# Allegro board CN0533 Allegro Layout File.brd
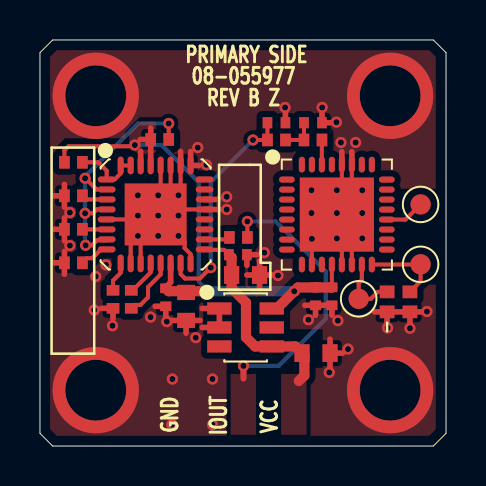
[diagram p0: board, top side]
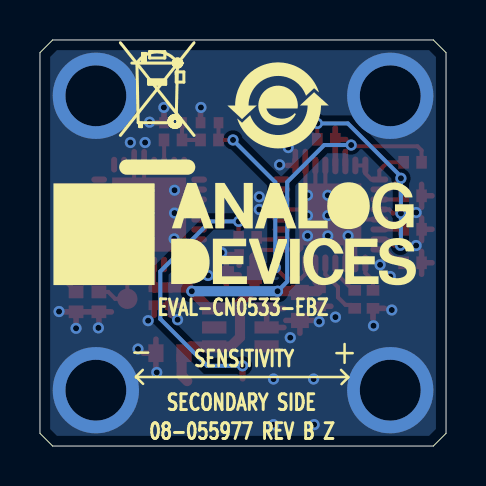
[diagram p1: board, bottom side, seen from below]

Outline 20.32 x 20.32 mm; copper layers: TOP, BOTTOM. Coordinates in mm from the lower left corner of the outline.
Outline path: 0,19.68 0.63,20.32 19.69,20.32 20.32,19.68 20.32,0.64 19.69,0 0.63,0 0,0.64 0,19.68

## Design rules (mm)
constraint set DEFAULT: min track width 0.203

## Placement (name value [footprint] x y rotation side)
C1  4700PF  [C0402]  13.66 16.18 180 top
C2  4700PF  [C0402]  11.83 16.18 180 top
C3  0.1uF  [C0402]  14.61 7.49 90 top
C4  1uF  [C0402]  13.79 7.49 90 top
C5  1uF  [C0603]  13.82 4.65 180 top
C6  0.1UF  [C0402]  9.9 9.58 180 top
C7  10UF  [C0603]  10.29 8.56 180 top
C8  0.1UF  [C0402]  6.3 7.44 90 top
C9  10uF  [C0603]  7.31 6.98 90 top
NOREF  -  []  19.69 0 90 top
NOREF#2  -  []  2.79 2.79 0 top
NOREF#3  -  []  -330.41 -227.36 0 top
NOREF#4  -  []  -233.94 -118.87 0 top
NOREF#5  -  []  11.61 28.17 0 top
NOREF#6  -  []  -206.25 31.75 0 top
NOREF#7  -  []  0.63 0 0 top
NOREF#8  -  []  0 0.64 0 top
NOREF#9  -  []  0 19.68 0 top
NOREF#10  -  []  61.64 260.07 0 top
NOREF#11  -  []  -330.41 -227.36 0 top
NOREF#12  -  []  -202.72 -33.5 0 top
NOREF#13  -  []  20.32 20.32 180 top
NOREF#14  -  []  -199.01 -56.36 0 top
NOREF#15  -  []  0 19.68 0 top
NOREF#16  -  []  2.79 2.79 0 top
NOREF#17  -  []  0 0 0 top
NOREF#18  -  []  20.32 0 90 top
NOREF#19  -  []  20.32 0.64 0 top
NOREF#20  -  []  0.63 20.32 0 top
NOREF#21  -  []  -46.48 223.98 0 top
NOREF#22  -  []  0 20.32 270 top
NOREF#23  -  []  19.69 0 0 top
NOREF#24  -  []  -198.96 -79.22 0 top
NOREF#25  -  []  10.08 9.32 180 bottom
NOREF#26  -  []  8.4 17.04 180 bottom
NOREF#27  -  []  14.65 13.64 180 bottom
R1  680  [R0402]  13.66 15.32 180 top
R2  1.3K  [R0402]  11.83 15.32 180 top
R3  15K  [R0402]  4.57 7.34 90 top
R4  0  [R0402]  3.66 7.34 270 top
R5  0  [R0402]  1.67 9.17 0 top
R6  0  [R0402]  1.67 10.85 0 top
R7  0  [R0402]  1.67 12.52 0 top
R8  100K  [R0402]  1.67 14.2 0 top
R9  0  [R0402]  9.93 10.44 0 top
R10  0  [R0402]  5.99 15.34 0 top
R11  470K  [R0402]  17.37 7.21 90 top
R12  470K  [R0402]  18.51 7.21 90 top
TP1  TESTPAD  [TPSMC40]  19.05 12.09 270 top
TP2  TESTPAD  [TPSMC40]  19.05 9.09 270 top
TP3  TESTPAD  [TPSMC40]  15.95 7.37 270 top
U1  ADXL1002BCPZ  [QFN32_5X5_PAD3_7X3_7]  14.86 11.58 270 top
U2  LT6654AMPS6-5#TRMPBF  [TSOT23_6]  10.29 5.93 270 top
U3  AD5749ACPZ  [QFN32_5X5_PAD3_1X3_1]  5.79 11.59 270 top

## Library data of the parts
C1 C2 = CAP: User Part Number: UPN; Tolerance: 10; alternate symbols: C0402L; part number: CAP_SM-4700PF,50V,10,E028612,C0402; tolerance: 10
C3 = CAP: User Part Number: UPN; Tolerance: 10; alternate symbols: C0402L; part number: CAP_SM-0.1UF,10V,10,E016510,C0402; tolerance: 10
C4 = CAP: User Part Number: UPN; Tolerance: 10; alternate symbols: C0402L; part number: CAP_SM-1UF,6.3V,10,E011561,C0402; tolerance: 10
C5 = CAP: User Part Number: UPN; Tolerance: 10; alternate symbols: C0603L; part number: CAP_SM-1UF,50V,10,E023087,C0603; tolerance: 10
C6 = CAP: User Part Number: UPN; Tolerance: 10; alternate symbols: C0402L; part number: CAP_SM-0.1UF,50V,10,E034665,C0402; tolerance: 10
C7 = CAP: User Part Number: UPN; Tolerance: 20; alternate symbols: C0603L; part number: CAP_SM-10UF,35V,20,E026762,C0603; tolerance: 20
C8 = CAP: User Part Number: UPN; Tolerance: 10; alternate symbols: C0402L; part number: CAP_SM-0.1UF,25V,10,E026964,C0402; tolerance: 10
C9 = CAP: User Part Number: UPN; Tolerance: 20; alternate symbols: C0603L; part number: CAP_SM-10UF,25V,20,E023693,C0603; tolerance: 20
R1 = RES: User Part Number: UPN; Tolerance: 1; alternate symbols: R0402L; part number: RES_SM-680,E015602,1/10W,1,R0402; tolerance: 1
R2 = RES: User Part Number: UPN; Tolerance: 1; alternate symbols: R0402L; part number: RES_SM-1.3K,E015613,1/10W,1,R0402; tolerance: 1
R3 = RES: User Part Number: UPN; Tolerance: 1; alternate symbols: R0402L; part number: RES_SM-15K,E007441,1/16W,1,R0402; tolerance: 1
R4-R7 R9 R10 = RES: User Part Number: UPN; Tolerance: 5; alternate symbols: R0402L; part number: RES_SM-0,E003438,N/A,5,R0402; tolerance: 5
R8 = RES: User Part Number: UPN; Tolerance: 5; alternate symbols: R0402L; part number: RES_SM-100K,E003464,1/10W,5,R0402; tolerance: 5
R11 R12 = RES: User Part Number: UPN; Tolerance: 5; alternate symbols: R0402L; part number: RES_SM-470K,E027137,1/10W,5,R0402; tolerance: 5
TP1-TP3 = NCTESTPAD: Tolerance: N/A; User Part Number: UPN; alternate symbols: (); part number: NCTESTPAD_SM-TESTPAD,E019801,TPSMC40; tolerance: N/A
U1 = ADXL100X: User Part Number: UPN; Tolerance: N/A; alternate symbols: (); part number: ADXL100X_SM-ADXL1002BCPZ,E026572,QFN32_5X5_PAD3_7X3_7; tolerance: N/A
U2 = LINLT6654: User Part Number: UPN; Tolerance: N/A; alternate symbols: (); part number: LINLT6654_SM-LT6654AMPS6-5#TRMPBF,E030329,TSOT23_6; tolerance: N/A
U3 = AD5749: User Part Number: UPN; Tolerance: N/A; alternate symbols: (); part number: AD5749_SM-AD5749ACPZ,E034718,QFN32_5X5_PAD3_1X3_1; tolerance: N/A

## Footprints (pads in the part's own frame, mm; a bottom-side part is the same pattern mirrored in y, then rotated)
C0402
  rect 0.483x0.559 smd: 1(-0.45,0) 2(0.45,0)
C0603
  rect 0.762x0.889 smd: 1(-0.7,0) 2(0.7,0)
QFN32_5X5_PAD3_1X3_1
  oval 0.305x0.889 smd: 1(-1.75,-2.45) 2(-1.25,-2.45) 3(-0.75,-2.45) 4(-0.25,-2.45) 5(0.25,-2.45) 6(0.75,-2.45) 7(1.25,-2.45) 8(1.75,-2.45) 17(1.75,2.45) 18(1.25,2.45) 19(0.75,2.45) 20(0.25,2.45) 21(-0.25,2.45) 22(-0.75,2.45) 23(-1.25,2.45) 24(-1.75,2.45)
  oval 0.889x0.305 smd: 9(2.45,-1.75) 10(2.45,-1.25) 11(2.45,-0.75) 12(2.45,-0.25) 13(2.45,0.25) 14(2.45,0.75) 15(2.45,1.25) 16(2.45,1.75) 25(-2.45,1.75) 26(-2.45,1.25) 27(-2.45,0.75) 28(-2.45,0.25) 29(-2.45,-0.25) 30(-2.45,-0.75) 31(-2.45,-1.25) 32(-2.45,-1.75)
  rect 3.099x3.099 smd: PAD(0,0)
QFN32_5X5_PAD3_7X3_7
  oval 0.305x0.787 smd: 1(-1.75,-2.5) 2(-1.25,-2.5) 3(-0.75,-2.5) 4(-0.25,-2.5) 5(0.25,-2.5) 6(0.75,-2.5) 7(1.25,-2.5) 8(1.75,-2.5) 17(1.75,2.5) 18(1.25,2.5) 19(0.75,2.5) 20(0.25,2.5) 21(-0.25,2.5) 22(-0.75,2.5) 23(-1.25,2.5) 24(-1.75,2.5)
  oval 0.787x0.305 smd: 9(2.5,-1.75) 10(2.5,-1.25) 11(2.5,-0.75) 12(2.5,-0.25) 13(2.5,0.25) 14(2.5,0.75) 15(2.5,1.25) 16(2.5,1.75) 25(-2.5,1.75) 26(-2.5,1.25) 27(-2.5,0.75) 28(-2.5,0.25) 29(-2.5,-0.25) 30(-2.5,-0.75) 31(-2.5,-1.25) 32(-2.5,-1.75)
  rect 3.708x3.708 smd: PAD(0,0)
R0402
  rect 0.635x0.737 smd: 1(-0.5,0) 2(0.5,0)
TPSMC40
  round 1.016 smd: 1(0,0)
TSOT23_6
  rect 0.61x1.219 smd: 1(-0.95,-1.31) 2(0,-1.31) 3(0.95,-1.31) 4(0.95,1.31) 5(0,1.31) 6(-0.95,1.31)

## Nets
AGND: C1.1 C2.1 C3.1 C4.1 C5.1 C6.1 C7.1 C8.1 C9.1 R4.2(N2) R5.1 R6.1 R7.1 R11.1 R12.1 U1.10 U1.13 U1.14 U1.27 U1.28(VSS_4) U1.PAD U2.1 U2.2 U3.5 U3.10 U3.11 U3.16 U3.21 U3.22 U3.25 U3.26 U3.27 U3.28 U3.PAD
VCC: C5.2(N2) C6.2(N2) C7.2(N2) U2.4 U3.17
VDD: C3.2(N2) C4.2(N2) C8.2(N2) C9.2(N2) R8.1 R10.1 U1.12 U2.6(VOUT) U3.14(VREF) U3.29 U3.30
AAF: C2.2(N2) R2.2(N2) U3.15
IOUT: R9.2(N2)
OR: TP1.1(N1) U1.20
UNNAMED_2_AD5749_I30_AD2: R4.1 U3.9
UNNAMED_2_AD5749_I30_CLEAR: R7.2(N2) U3.3
UNNAMED_2_AD5749_I30_CLRSEL: R10.2(N2) U3.2 U3.4 U3.7
UNNAMED_2_AD5749_I30_FAULT: R8.2(N2) U3.1 U3.31 U3.32
UNNAMED_2_AD5749_I30_IOUT: R9.1 U3.18
UNNAMED_2_AD5749_I30_REXT1: R3.1 U3.13
UNNAMED_2_AD5749_I30_REXT2: R3.2(N2) U3.12
UNNAMED_2_AD5749_I30_SDIN: R5.2(N2) U3.8
UNNAMED_2_AD5749_I30_SYNCN: R6.2(N2) U3.6
UNNAMED_2_ADXL100X_I1_ST: R12.2(N2) TP2.1(N1) U1.16
UNNAMED_2_ADXL100X_I1_STANDBY: R11.2(N2) TP3.1(N1) U1.15
UNNAMED_2_ADXL100X_I1_VOUT: R1.1 U1.30
UNNAMED_2_CAP_I14_N2: C1.2(N2) R1.2(N2) R2.1

Pads without a net: U1 1 2 3 4 5 6 7 8 9 11 17 18 19 21 22 23 24 25 26 29 31 32; U2 3 5; U3 19 20 23 24

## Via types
v1: diameter 0.559, hole 0.305, TOP to BOTTOM, 60 vias
v2: diameter 4.318, hole 3.048, TOP to BOTTOM, 4 vias

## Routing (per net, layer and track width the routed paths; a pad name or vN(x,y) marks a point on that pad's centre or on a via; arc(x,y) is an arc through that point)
AGND: length 49
  TOP w0.203: U1.14 15.61,9.87 v1(16.13,10.39) ; v1(6.93,11.53) 7.24,11.84 U3.21 ; U3.11 5.04,10.1 4.98,10.16 4.98,10.44 v1(4.9,10.52) 4.54,10.15 U3.10 ; U3.28 6.04,13.08 5.92,12.95 v1(5.92,12.55) ; U3.27 6.54,12.94 v1(6.93,12.55) 6.93,12.93 7.04,13.04 U3.26 ; v1(4.9,11.53) 4.52,11.53 4.33,11.34 U3.5 ; U3.16 7.54,9.6 7.24,9.91 7.24,10.21 v1(6.93,10.52) ; v1(14.86,12.8) 15.11,13.05 U1.28 ; U1.10 v1(13.61,10.37) ; U1.13 15.11,10.14 v1(14.86,10.39) ; U1.27 15.61,13.32 v1(16.13,12.8)
  TOP w0.279: C5.1 14.52,5.35 ; C5.1 15.15,4.65 ; C5.1 14.52,3.95 ; 14.11,16.71 C1.1 14.61,16.18 ; U1.27 15.61,14.73 ; R6.1 1.22,11.42 ; R6.1 1.22,10.27 ; R6.1 0.7,10.85 ; U3.22 8.94,12.34 ; C2.1 12.28,16.71 ; U3.26 7.04,14.74 ; 14.61,6.55 C3.1 C4.1 ; 10.35,8.56 C7.1 ; C7.1 10.99,7.86 ; C7.1 11.63,8.56 ; C7.1 10.99,9.26 ; 16.75,6.71 R11.1 ; R11.1 17.37,6.14 ; R11.1 R12.1 ; 6.3,6.5 C8.1 5.76,6.99 ; 13.79,6.55 C4.1 ; C4.1 13.26,7.04 ; 7.31,5.65 C9.1 ; C9.1 8.01,6.28 ; C9.1 6.61,6.28 ; 1.22,8.6 R5.1 ; R5.1 0.7,9.17 ; R5.1 1.22,9.74 ; R12.1 19.14,6.71 ; R12.1 18.51,6.14 ; 10.35,9.04 C6.1 10.85,9.58 ; U1.28 15.11,14.73 ; 3.08,6.89 R4.2 3.66,6.37 ; 7.54,14.74 U3.25 7.95,14.04 ; 8.12,6.88 U2.1 U2.2 8.12,5.93 ; 1.22,11.95 R7.1 ; R7.1 0.7,12.52 ; R7.1 1.22,13.09 ; U3.21 8.94,11.84
  vias: v1(1.5,11.68) v1(1.5,10.03) v1(2.72,6.81) v1(2.79,8.48) v1(3.3,9.07) v1(3.63,6.02) v1(4.9,12.55) v1(5.53,6.45) v1(5.92,11.53) v1(5.92,10.52) v1(6.35,6.22) v1(6.63,3.35) v1(6.6,1.07) v1(7.8,5.42) v1(7.9,14.94) v1(8.33,14.07) v1(8.63,3.35) v1(8.63,1.07) v1(9.34,12.47) v1(9.34,11.84) v1(11.22,9.68) v1(11.91,8.53) v1(12.27,16.94) v1(13.43,6.32) v1(13.59,12.8) v1(13.59,11.66) v1(14.12,16.94) v1(14.48,3.68) v1(14.84,16.21) v1(14.86,11.66) v1(14.91,6.27) v1(15.06,15.19) v1(15.42,4.85) v1(15.8,15.19) v1(16.13,11.66) v1(17.4,5.91) v1(18.51,5.89) v1(19.36,6.73) v2(2.79,17.53) v2(2.79,2.79) v2(17.52,17.53) v2(17.52,2.79)
VCC: length 10.5
  TOP w0.203: C6.2 9.21,9.82 8.26,9.82 U3.17
  TOP w0.508: C6.2 9.59,9.44 C7.2 9.59,7.9 10.31,7.18 10.31,5.44 10.77,4.98 U2.4 12.78,4.98 C5.2 13.23,4.53 13.23,3.53 12.95,3.25
VDD: length 29.6
  TOP w0.203: 14.63,7.93 14.61,7.96 U1.12 ; v1(4.75,15.06) 4.68,15 1.43,15 1.22,14.8 R8.1
  TOP w0.279: U3.29 5.54,14.74 ; U3.14 6.54,8.19 6.3,7.95 C8.2 ; 5.02,15.34 R10.1 ; R10.1 5.54,14.77 ; R10.1 5.54,15.91 ; U3.30 5.04,14.74
  TOP w0.508: 14.6,7.93 14.63,7.93 ; 14.6,7.93 C3.2 ; 14.6,7.93 13.78,7.93 ; 7.37,7.75 6.44,7.75 C8.2 ; 7.37,7.75 7.45,7.75 ; 7.37,7.75 C9.2 ; 13.78,7.93 C4.2 ; 13.78,7.93 12.91,7.93 v1(12.72,7.75) 11.86,6.88 U2.6 ; 7.45,7.75 v1(8.43,7.75) ; 7.45,7.75 7.39,7.69
  BOTTOM w0.203: v1(4.75,15.06) 6.09,15.06 7.95,13.21 7.95,8.23 v1(8.43,7.75)
  BOTTOM w0.508: v1(8.43,7.75) v1(12.72,7.75)
AAF: length 11.2
  TOP w0.203: U3.15 7.04,8.61 7.26,8.38 8,8.38 v1(8.54,8.93) ; C2.2 R2.2 v1(10.66,15.32)
  BOTTOM w0.203: v1(10.66,15.32) 8.54,13.2 v1(8.54,8.93)
IOUT: length 13.9
  TOP w0.203: R9.2 v1(10.38,11.24)
  TOP w0.305: 10.18,3.38 v1(10.18,4.01)
  BOTTOM w0.203: v1(10.38,11.24) 11.8,11.24 14.3,8.74 14.3,6.36 11.95,4.01 v1(10.18,4.01)
OR: length 2
  TOP w0.203: U1.20 18.29,11.33 TP1.1
UNNAMED_2_AD5749_I30_AD2: length 1.5
  TOP w0.203: R4.1 3.66,8.28 4.04,8.66 U3.9
UNNAMED_2_AD5749_I30_CLEAR: length 1.3
  TOP w0.203: R7.2 2.31,12.34 U3.3
UNNAMED_2_AD5749_I30_CLRSEL: length 13.2
  TOP w0.203: R10.2 v1(6.44,16.14) ; U3.2 2.83,12.84 2.27,13.4 v1(2.26,13.4) ; v1(2.26,11.65) 2.65,11.65 2.85,11.84 U3.4 ; U3.7 3.3,10.3 2.86,10.3 2.61,10.05 v1(2.28,10.05)
  BOTTOM w0.203: v1(2.28,10.05) 2.26,10.07 v1(2.26,11.65) v1(2.26,13.4) 2.26,13.49 4.91,16.14 v1(6.44,16.14)
UNNAMED_2_AD5749_I30_FAULT: length 3.6
  TOP w0.203: U3.31 U3.32 4.04,13.64 3.74,13.34 U3.1 3.34,13.78 2.92,14.2 R8.2
UNNAMED_2_AD5749_I30_IOUT: length 1.3
  TOP w0.203: R9.1 9.38,10.34 U3.18
UNNAMED_2_AD5749_I30_REXT1: length 3
  TOP w0.203: U3.13 6.04,8.59 5.41,7.96 5.41,7.44 5.03,7.06 4.74,7.06 R3.1
UNNAMED_2_AD5749_I30_REXT2: length 1.8
  TOP w0.203: R3.2 4.64,7.79 5.54,8.69 U3.12
UNNAMED_2_AD5749_I30_SDIN: length 1.5
  TOP w0.203: U3.8 3.06,9.84 2.61,9.4 2.35,9.4 R5.2
UNNAMED_2_AD5749_I30_SYNCN: length 1.2
  TOP w0.203: U3.6 2.13,10.84 R6.2
UNNAMED_2_ADXL100X_I1_ST: length 4
  TOP w0.203: U1.16 19.04,9.08 TP2.1 19.05,8.25 R12.2
UNNAMED_2_ADXL100X_I1_STANDBY: length 3.3
  TOP w0.203: R11.2 16.91,7.71 16.56,7.37 TP3.1 15.95,8.15 16.11,8.31 U1.15
UNNAMED_2_ADXL100X_I1_VOUT: length 1.2
  TOP w0.203: U1.30 14.11,15.31 R1.1
UNNAMED_2_CAP_I14_N2: length 1.8
  TOP w0.203: R2.1 R1.2 C1.2

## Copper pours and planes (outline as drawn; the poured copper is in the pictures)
AGND on TOP: 0.84,0.51 0.51,0.85 0.51,19.47 0.84,19.81 19.47,19.81 19.81,19.47 19.81,12.88 17.83,12.88 17.83,8.68 17.03,8.68 17.02,8.65 16.85,8.46 16.61,8.38 16.54,8.35 16.51,8.28 16.51,8.08 16.69,7.95 16.83,7.77 17.08,7.77 17.08,8.07 17.17,8.28 17.38,8.37 17.83,8.37 17.83,8.08 19.81,8.08 19.81,0.85 19.47,0.51 ; 3 cut-outs
AGND on TOP: 7,0.56 7,3.61 8.27,3.61 8.27,0.56
AGND on BOTTOM: 0.84,0.51 0.51,0.85 0.51,19.47 0.84,19.81 19.47,19.81 19.81,19.47 19.81,0.85 19.47,0.51 ; 1 cut-out
VCC on TOP: 12.07,3.61 12.07,0.56 13.34,0.56 13.34,3.61
VDD on TOP: 4.47,15.65 4.47,14.91 4.9,14.48 4.9,14.22 5.81,14.22 5.81,16.26 5.08,16.26
IOUT on TOP: 9.54,3.61 9.54,0.56 10.81,0.56 10.81,3.61

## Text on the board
Ref Des/Silkscreen Bottom: SENSITIVITY | EVAL-CN0533-EBZ | 08-055977 REV B Z | SECONDARY SIDE
Ref Des/Silkscreen Top: 08-055977 | REV B Z | PRIMARY SIDE | GND | IOUT | VCC
PAGE_OUTLINE: 23JAN19 | B | PER ECR-092728 | 17JAN20 | M.SADEGHI | ADXL1002 4-20mA
DIMENSION: DIA MAX | (REF)
User.15: 15.    BOARDS TO BE PANELIZED AND SHIP INTACT.
User.45: FIGURE | SIZE | 12.0 | 120.0 | PLATED | FINISHED HOLES IN MILS | ALL UNITS ARE IN MILS | QTY | 60 | 4 | TOLERANCE/NOTES
